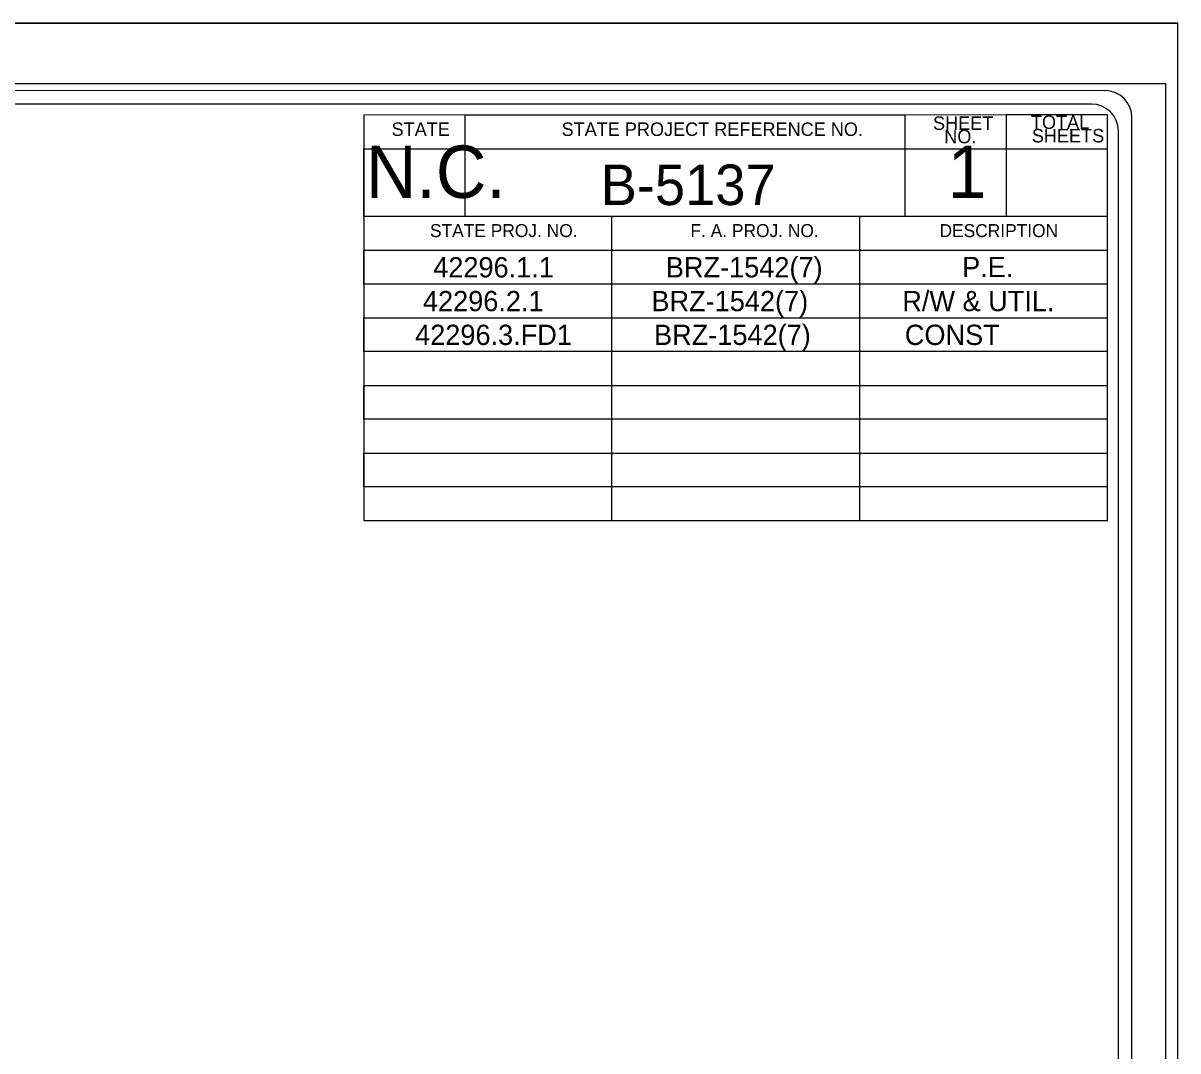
# Model space of a CAD drawing. Extents: x 1664524 to 1666208, y 587901 to 592296.
# Drawn here: x 1665780.8 to 1666207.8, y 591916.2 to 592296.3 of the extents above; entities that cross this region are included whole.
import ezdxf

# ---------------------------------------------------------------- set-up
doc = ezdxf.new("R2010")
doc.units = 0
for name, color, linetype in [('Prop Horizontal Alignment', 7, 'Continuous'), ('Prop Horizontal Alignment Station Label', 7, 'Continuous'), ('Prop Horizontal Alignment Tick Large', 7, 'Continuous'), ('Prop Horizontal Alignment Tick Small', 7, 'Continuous'), ('Sheet Cutting Line CELL', 7, 'Continuous')]:
    doc.layers.add(name, color=color, linetype=linetype)

msp = doc.modelspace()

# ---------------------------------------------------------------- linework, layer by layer
at = {"layer": 'Prop Horizontal Alignment Station Label'}
for points in [[(1666180.77, 592271.34), (1664700.75, 592271.35)], [(1666175.76, 592266.34), (1664755.77, 592266.34)], [(1665906.76, 592112.35), (1666181.76, 592112.35), (1666181.76, 592124.84), (1665906.76, 592124.85), (1665906.76, 592137.34), (1666181.76, 592137.34), (1666181.76, 592149.84), (1665906.77, 592149.84), (1665906.76, 592162.35), (1666181.76, 592162.35), (1666181.76, 592174.85), (1665906.76, 592174.85), (1665906.76, 592187.34), (1666181.76, 592187.35), (1666181.76, 592199.84), (1665906.76, 592199.84), (1665906.76, 592212.34), (1666181.76, 592212.34), (1666181.76, 592224.85), (1665906.76, 592224.85), (1665906.76, 592249.85), (1666181.76, 592249.85), (1666181.76, 592262.35), (1665906.76, 592262.34), (1665906.76, 592112.35), (1665998.41, 592112.34), (1665998.41, 592224.84), (1665944.26, 592224.84), (1665944.26, 592262.35), (1666106.77, 592262.34), (1666106.76, 592224.85), (1666090.06, 592224.85), (1666090.06, 592112.35), (1666181.76, 592112.35), (1666181.76, 592262.35), (1666144.26, 592262.35), (1666144.27, 592224.85)], [(1666190.76, 591231.35), (1666190.76, 592261.34)], [(1666185.76, 591421.34), (1666185.76, 592256.35)]]:
    msp.add_lwpolyline(points, dxfattribs=at)
for centre in [(1666180.76, 592261.39), (1666175.76, 592256.39)]:
    msp.add_arc(centre, 10, 0, 90, dxfattribs=at)
at = {"layer": 'Prop Horizontal Alignment Tick Large'}
msp.add_lwpolyline([(1664536.76, 591218.79), (1666203.26, 591218.79), (1666203.26, 592273.89), (1664536.76, 592273.89)], close=True, dxfattribs=at)
at = {"layer": 'Prop Horizontal Alignment Tick Small'}
msp.add_lwpolyline([(1666207.76, 592296.34), (1664523.76, 592296.34), (1664523.76, 591196.35), (1666207.76, 591196.35)], close=True, dxfattribs=at)
at = {"layer": 'Sheet Cutting Line CELL'}
msp.add_line((1664523.76, 592296.34), (1666207.76, 592296.34), dxfattribs=at)

# ---------------------------------------------------------------- texts
at = {"layer": 'Prop Horizontal Alignment'}
for s, height, p in [('B-5137', 15, (1665994.32, 592229.04)), ('42296.1.1', 7.5, (1665932.41, 592202.29)), ('BRZ-1542(7)', 7.5, (1666018.41, 592202.29)), ('P.E.', 7.5, (1666127.97, 592202.39)), (' 42296.2.1 ', 7.5, (1665925.82, 592189.79)), (' BRZ-1542(7)   ', 7.5, (1666010.3, 592189.79)), ('R/W & UTIL.', 7.5, (1666105.85, 592189.8)), ('42296.3.FD1', 7.5, (1665925.71, 592177.3)), ('BRZ-1542(7)   ', 7.5, (1666014.05, 592177.3)), ('CONST     ', 7.5, (1666106.79, 592177.3))]:
    msp.add_text(s, height=height, dxfattribs=at).set_placement(p)
at = {"layer": 'Prop Horizontal Alignment Station Label'}
for s, height, p in [('STATE', 5, (1665917.01, 592254.6)), ('STATE PROJECT REFERENCE NO.', 4.9998, (1665979.86, 592254.59)), ('SHEET', 5, (1666117.21, 592256.84)), ('TOTAL', 5, (1666153.41, 592257.2)), ('NO.', 5, (1666121.36, 592251.9)), ('SHEETS', 5, (1666153.75, 592252.2)), ('N.C.', 19.35, (1665907.51, 592231.7)), ('1', 19.35, (1666122.61, 592231.7)), ('STATE PROJ. NO.', 4.8, (1665931.21, 592217.2)), ('F. A. PROJ. NO.', 4.8, (1666027.51, 592217.2)), ('DESCRIPTION', 4.8, (1666119.61, 592217.19))]:
    msp.add_text(s, height=height, rotation=360, dxfattribs=at).set_placement(p)

doc.saveas('drawing.dxf')
